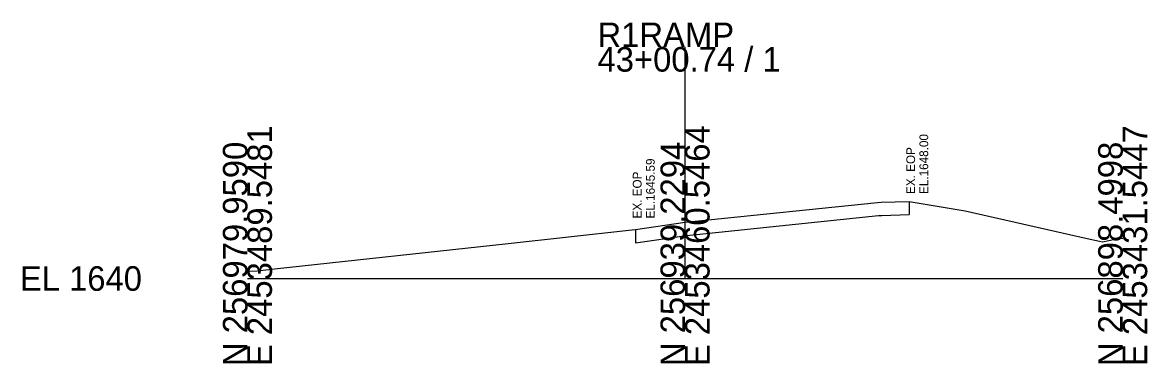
# Model space of a CAD drawing. Extents: x 104 to 233, y 12385 to 16924.
# Drawn here: x 104.5 to 233, y 16884.8 to 16923.7 of the extents above; entities that cross this region are included whole.
import ezdxf

# ---------------------------------------------------------------- set-up
doc = ezdxf.new("R2010")
doc.units = 0
for name, color, linetype in [('DESIGN - SHEET - Light Grid', 7, 'Continuous'), ('SURVEY - GROUND - Existing Pavement Layer', 7, 'Continuous'), ('SURVEY - GROUND - Existing Pavement Text', 7, 'Continuous'), ('SURVEY - GROUND - Top of Ground', 7, 'Continuous')]:
    doc.layers.add(name, color=color, linetype=linetype)

msp = doc.modelspace()

# ---------------------------------------------------------------- linework, layer by layer
at = {"layer": 'DESIGN - SHEET - Light Grid'}
for p, q in [((180.15, 16894.49), (180.15, 16920.89)), ((130.15, 16894.49), (180.15, 16894.49)), ((180.15, 16894.49), (230.15, 16894.49))]:
    msp.add_line(p, q, dxfattribs=at)
at = {"layer": 'SURVEY - GROUND - Existing Pavement Layer'}
for p, q in [((205.74, 16903.29), (205.74, 16901.79)), ((174.48, 16900.08), (174.48, 16898.56))]:
    msp.add_line(p, q, dxfattribs=at)
msp.add_lwpolyline([(174.48, 16898.56), (180.33, 16899.41), (181.47, 16899.52), (202.24, 16901.67), (202.63, 16901.69), (205.74, 16901.79)], dxfattribs=at)
at = {"layer": 'SURVEY - GROUND - Top of Ground'}
msp.add_lwpolyline([(130.15, 16895.34), (131.28, 16895.38), (133.26, 16895.61), (159.93, 16898.48), (173.71, 16900), (174.48, 16900.08), (180.15, 16900.9), (180.15, 16900.9), (180.15, 16900.9), (181.32, 16901.02), (202.13, 16903.17), (202.57, 16903.19), (205.74, 16903.29), (212.14, 16902.22), (226.11, 16899.06), (227.49, 16898.76), (227.83, 16898.68), (229.31, 16898.97), (230.15, 16899.09)], dxfattribs=at)

# ---------------------------------------------------------------- texts
at = {"layer": 'DESIGN - SHEET - Light Grid'}
for s, p in [('R1RAMP', (170.15, 16920.89)), ('43+00.74 / 1', (170.15, 16918.09)), ('EL 1640', (104.15, 16893.09))]:
    msp.add_text(s, height=2.8, dxfattribs=at).set_placement(p)
for s, p in [('E 2453489.5481', (132.95, 16884.49)), ('E 2453460.5464', (182.95, 16884.49)), ('E 2453431.5447', (232.95, 16884.49)), ('N 256979.9590', (130.15, 16884.49)), ('N 256939.2294', (180.15, 16884.49)), ('N 256898.4998', (230.15, 16884.49))]:
    msp.add_text(s, height=2.8, rotation=90, dxfattribs=at).set_placement(p)
at = {"layer": 'SURVEY - GROUND - Existing Pavement Text'}
for s, p in [('EL.1648.00', (207.93, 16904.13)), ('EX. EOP', (206.43, 16904.13)), ('EL.1645.59', (176.69, 16901.34)), ('EX. EOP', (175.18, 16901.34))]:
    msp.add_text(s, height=1, rotation=90, dxfattribs=at).set_placement(p)

doc.saveas('drawing.dxf')
